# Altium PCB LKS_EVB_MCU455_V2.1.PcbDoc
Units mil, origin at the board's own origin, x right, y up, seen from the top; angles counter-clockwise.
Board outline 8180 x 3528.01 mil, 2 copper layers (Top Layer, Bottom Layer); 55 components, 86 nets, 295 pads, 79 vias.
Unrouted connection lines stored in the file: 39.
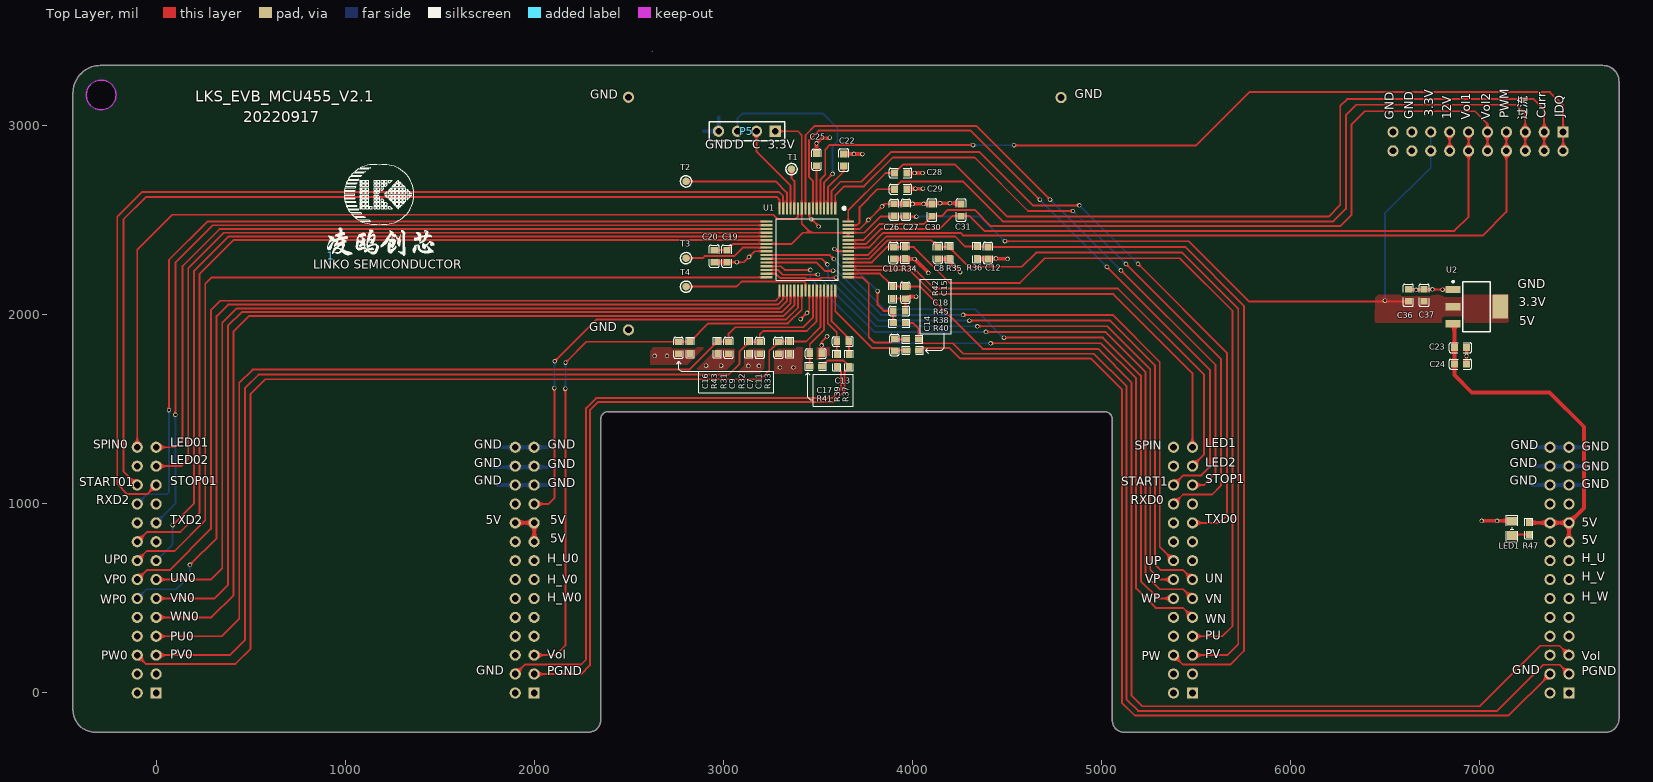
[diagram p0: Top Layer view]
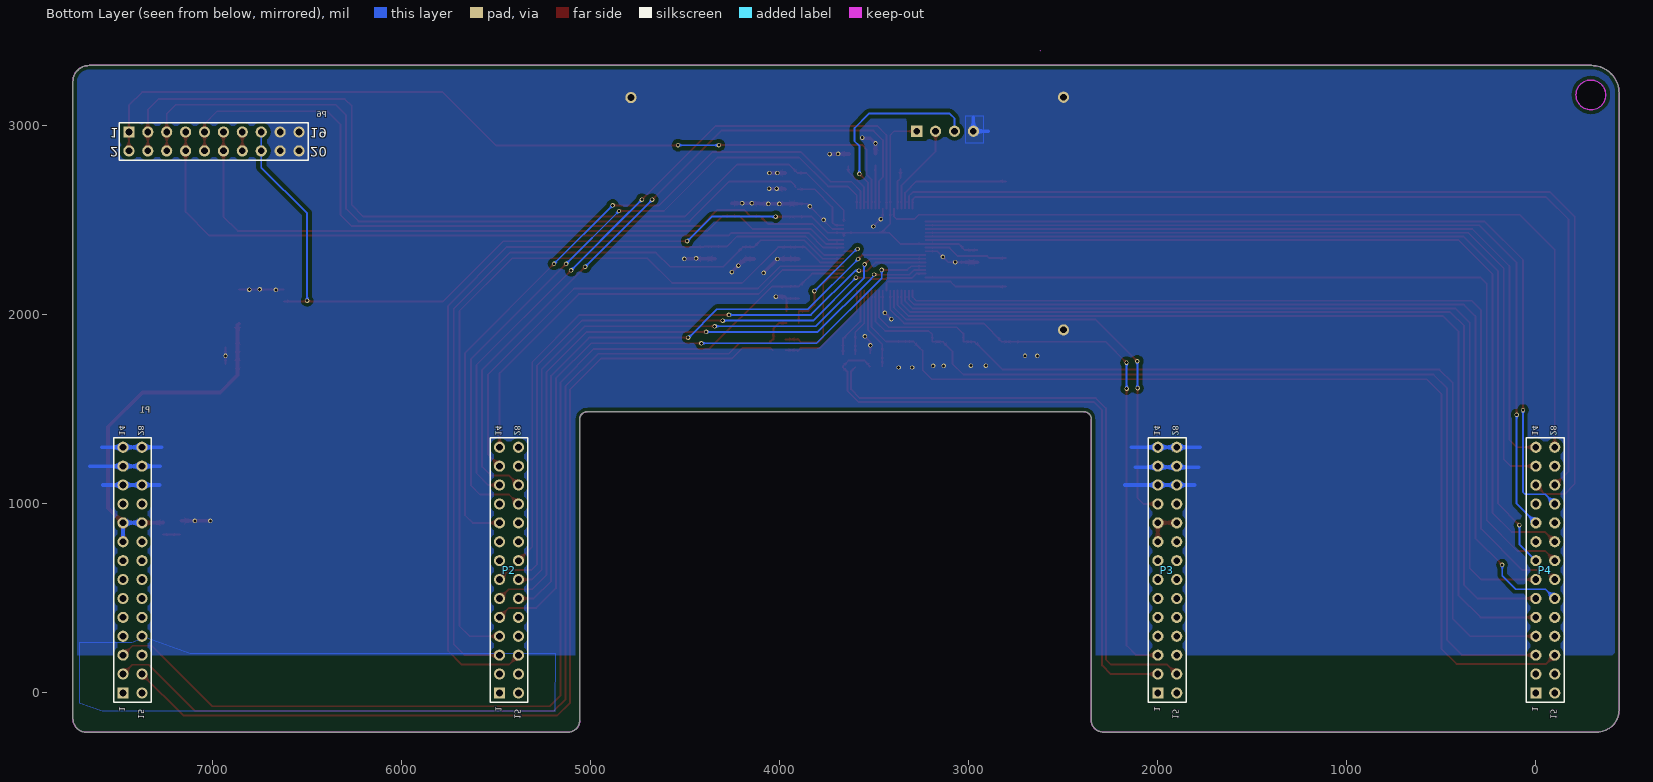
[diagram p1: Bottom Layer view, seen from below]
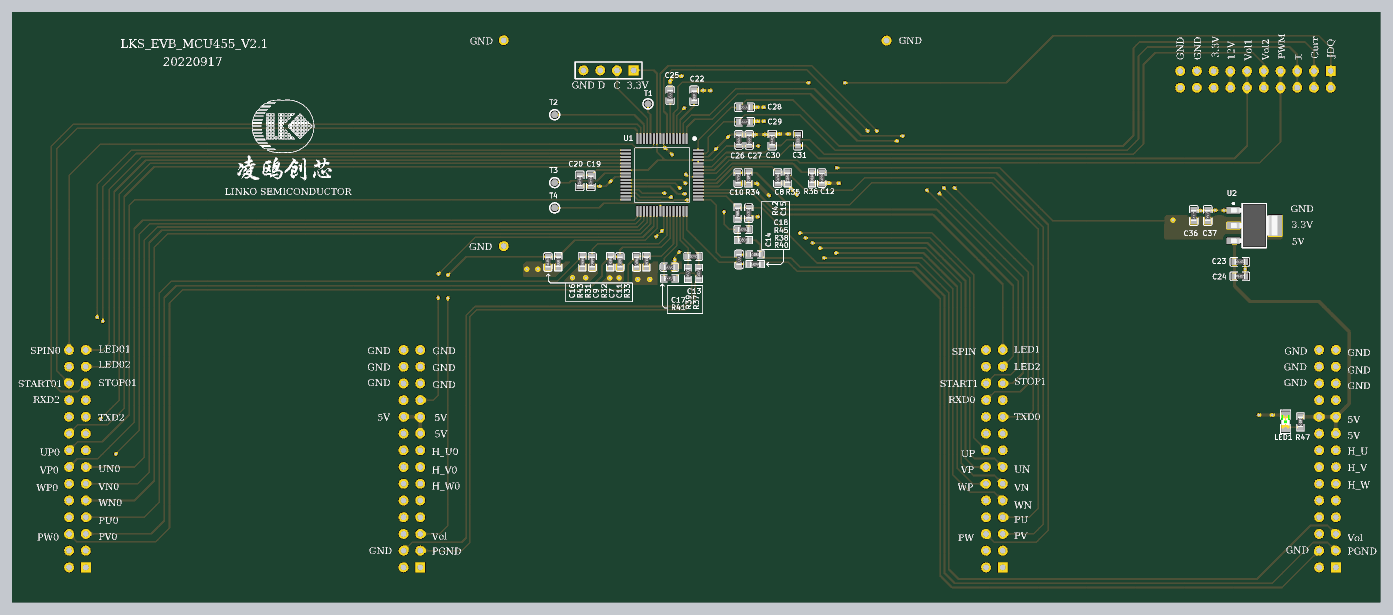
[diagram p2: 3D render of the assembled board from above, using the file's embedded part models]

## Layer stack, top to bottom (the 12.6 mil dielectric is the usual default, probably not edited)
Top Solder: solder mask 0.4, Solder Resist, Dk 3.5
Top Layer: signal copper 1.4
Dielectric1: dielectric 12.6, FR-4, Dk 4.8
Bottom Layer: signal copper 1.4
Bottom Solder: solder mask 0.4, Solder Resist, Dk 3.5

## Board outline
-440,-91 ccw(c-324,-91) -324,-207 2288.99,-207 ccw(c2288.99,-143.67) 2352.32,-143.67 2352.32,1448.33 cw(c2392,1448.33) 2392,1488.01 5018,1488.01 cw(c5018,1446.67) 5059.33,1446.67 5059.33,-146.33 ccw(c5121,-146.33) 5121,-208 7669,-208 ccw(c7669,-137) 7740,-137 7740,3235 ccw(c7654.99,3235) 7654.99,3320.01 -294.32,3320.01 ccw(c-294.32,3174.33) -440,3174.33
cut-out: -291,3085.26 cw(c-291,3164) -369.74,3164 cw(c-291,3164) -291,3242.74 cw(c-291,3164) -212.26,3164 cw(c-291,3164)

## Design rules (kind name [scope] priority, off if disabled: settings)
Clearance Clearance_1 [INPolygon] p1: gap=20 ignorepadtopadclearanceinfootprint=FALSE except(0: Arc-Hole Track-Hole SMDPad-Hole THPad-Hole Via-Hole Fill-Hole Poly-Hole Region-Hole Text-Hole)
Clearance [All] p2: gap=5 ignorepadtopadclearanceinfootprint=FALSE
ComponentClearance [All] p1: gap=0 collisioncheckmode=3 verticalgap=0 showdistances=FALSE
MinimumSolderMaskSliver [All] p1 off: minsoldermaskwidth=10
PolygonConnect [All] p1: connectstyle=Direct reliefconductorwidth=20 reliefentries=4 polygonreliefangle="90 Angle" airgapwidth=10
RoutingVias [All] p1: holewidth=12 width=20 viastyle="Through Hole" minholewidth=0 minwidth=10 maxholewidth=100 maxwidth=200
SilkToSilkClearance [All] p1 off: silktosilkclearance=10
SilkToSolderMaskClearance SilkscreenOverComponentPads [IsPad] p1 off: minsilkscreentomaskgap=10 clearancetoexposedcopper=TRUE
SolderMaskExpansion [All] p1: expansion=4 istentingtop=FALSE
Width [All] p1: maxlimit=100 minlimit=1 preferedwidth=10
26 further rules are at their usual default settings.

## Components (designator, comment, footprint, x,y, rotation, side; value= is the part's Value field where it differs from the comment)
1 "LKS_sign" LKS_LOGO2 924,2313 r0 top
C7 "1nF/16V" 0603C 3194,1826.01 r270 top
C8 "1nF/16V" 0603C 4137,2327.99 r270 top
C9 "1nF/16V" 0603C 3029,1826.01 r270 top
C10 "1nF/16V" 0603C 3900.5,2327.99 r270 top
C11 "1nF/16V" 0603C 3293,1826.01 r270 top
C12 "1nF/16V" 0603C 4400.67,2327.99 r270 top
C13 "1nF/10V" 0603C 3633,1859 r180 top
C14 "1nF/10V" 0603C 3906,1841 r270 top
C15 "100nF/50V" 0603C 3964,2118 r90 top
C16 "100nF/50V" 0603C 2763.33,1826.01 r90 top
C17 "1nF/50V" 0603C 3490,1795 r180 top
C18 "1nF/50V" 0603C 3932,2021 r180 top
C19 "10uF/10V" 0603C 3019.67,2310.99 r270 top
C20 "100nF/10V" 0603C 2953,2311 r270 top
C22 "100nF/10V" 0603C 3638,2820 r90 top
C23 "10uF/10V" 0603C 6901,1827 r0 top
C24 "100nF/10V" 0603C 6901,1740 r0 top
C25 "100nF/50V" 0603C 3494,2822 r90 top
C26 "10uF/10V" 0603C 3905,2556 r90 top
C27 "100nF/10V" 0603C 3967,2556 r90 top
C28 "100pF/10V" 0603C 3939,2751 r0 top
C29 "100pF/10V" 0603C 3939,2665 r0 top
C30 "100pF/10V" 0603C 4105,2555 r90 top
C31 "100pF/10V" 0603C 4259,2555 r90 top
C36 "10uF/10V" 0603C 6625,2104 r90 top
C37 "100nF/10V" 0603C 6709,2104 r90 top
LED1 "LED" LED_0805R 7174,871 r90 top
P1 "Header 14X2A" HDR2X14_CEN 7475,0 r90 bottom locked
P2 "Header 14X2A" HDR2X14_CEN 5483,0 r90 bottom locked
P3 "Header 14X2A" HDR2X14_CEN 2000,0 r90 bottom locked
P4 "Header 14X2A" HDR2X14_CEN 0,0 r90 bottom locked
P5 "Header 4" HDR1X4 3276,2972 r180 top
P6 "Header 10X2" HDR2X10 7444.02,2967.99 r180 bottom
R31 "1K" 0603R 2969,1827.51 r270 top value=K
R32 "1K" 0603R 3136,1827.51 r270 top value=K
R33 "1K" 0603R 3352,1827.51 r270 top value=K
R34 "1K" 0603R 3962,2329 r270 top value=K
R35 "1K" 0603R 4197,2329.49 r270 top value=K
R36 "1K" 0603R 4342,2329.49 r270 top value=K
R37 "1K1%" 0603R 3666,1758 r90 top value=K
R38 "1K1%" 0603R 4002,1871 r180 top value=K
R39 "1K1%" 0603R 3601.33,1758.01 r90 top value=K
R40 "1K1%" 0603R 4003,1813 r180 top value=K
R41 "1K1%" 0603R 3490,1728 r0 top value=K
R42 "1K1%" 0603R 3897,2119 r90 top value=K
R43 "1K1%" 0603R 2825,1827.51 r90 top value=K
R45 "1K1%" 0603R 3932,1957 r0 top value=K
R47 "330R" 0603R 7263,870 r270 top value=330
T1 "TestP" TP-40 3362,2772 r0 top
T2 "TestP" TP-40 2804,2707 r0 top
T3 "TestP" TP-40 2804,2301 r0 top
T4 "TestP" TP-40 2804,2150 r0 top
U1 "LKS32MC455RCT8" LQFP64 3593.17,2557.17 r180 top
U2 "AMS1117-3.3V" DCY0004A_M 6987,2044 r0 top

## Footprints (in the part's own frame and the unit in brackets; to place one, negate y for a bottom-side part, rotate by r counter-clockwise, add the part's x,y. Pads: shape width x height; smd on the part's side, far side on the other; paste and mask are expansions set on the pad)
0603C [mm]
  rect 0.9x0.95 smd: 1(-0.813,0) 2(0.813,0)
  silkscreen extent -1.42,-0.64 1.42,0.64, body extent -0.8,-0.4 0.8,0.4, height 0.45
0603R [mil]
  rect 38x32 smd: 1(-32,0) 2(32,0)
  silkscreen extent -55,-22 55,22, body extent -31,-16 32,16, height 18
DCY0004A_M [mm] "SOT223, 4-Leads, Body 6.7x3.7mm, Pitch 2.3mm, IPC Low Density"
  rrect10% 2.05x1 smd: 1(-3.175,2.3) 2(-3.175,0) 3(-3.175,-2.3)
  rrect5% 2.05x3.25 smd: 4(3.175,0)
  silkscreen extent -3.3,-3.35 1.85,3.47, body extent -3.5,-3.25 3.5,3.25, height 1.62
HDR1X4 [mm] "Connector; Header; 4 Position"
  rect 1.5x1.5 hole 0.9: 1(0,0)
  round 1.5 hole 0.9: 2(2.54,0) 3(5.08,0) 4(7.62,0)
  silkscreen extent -1.27,-1.27 8.89,1.27
HDR2X10 [mm] "Connector; Header; 10x2 Position"
  rect 1.5x1.5 hole 0.9: 1(0,0)
  round 1.5 hole 0.9: 2(0,-2.54) 3(2.54,0) 4(2.54,-2.54) 5(5.08,0) 6(5.08,-2.54) 7(7.62,0) 8(7.62,-2.54) 9(10.16,0) 10(10.16,-2.54) 11(12.7,0) 12(12.7,-2.54) 13(15.24,0) 14(15.24,-2.54) 15(17.78,0) 16(17.78,-2.54) 17(20.32,0) 18(20.32,-2.54) 19(22.86,0) 20(22.86,-2.54)
  silkscreen extent -1.27,-3.81 24.13,1.27
HDR2X14_CEN [mm] "Connector; Header; 14x2 Position"
  rect 1.5x1.5 hole 0.9: 1(0,0)
  round 1.5 hole 0.9: 2(2.54,0) 3(5.08,0) 4(7.62,0) 5(10.16,0) 6(12.7,0) 7(15.24,0) 8(17.78,0) 9(20.32,0) 10(22.86,0) 11(25.4,0) 12(27.94,0) 13(30.48,0) 14(33.02,0) 15(0,-2.54) 16(2.54,-2.54) 17(5.08,-2.54) 18(7.62,-2.54) 19(10.16,-2.54) 20(12.7,-2.54) 21(15.24,-2.54) 22(17.78,-2.54) 23(20.32,-2.54) 24(22.86,-2.54) 25(25.4,-2.54) 26(27.94,-2.54) 27(30.48,-2.54) 28(33.02,-2.54)
  silkscreen extent -1.27,-3.81 34.29,1.27
LED_0805R [mil] "LED"
  rect 46x51.18 smd: 1(-38,0) 2(38,0)
  silkscreen extent -70,-31 70,31, body extent -39,-25 39,25, height 32
LKS_LOGO2 [mil] "标?"
  silkscreen extent 70,167 440,482
LQFP64 [mm]
  rect 0.3x1.6 smd: 1(0,-0.15) 2(0.5,-0.15) 3(1,-0.15) 4(1.5,-0.15) 5(2,-0.15) 6(2.5,-0.15) 7(3,-0.15) 8(3.5,-0.15) 9(4,-0.15) 10(4.5,-0.15) 11(5,-0.15) 12(5.5,-0.15) 13(6,-0.15) 14(6.5,-0.15) 15(7,-0.15) 16(7.5,-0.15) 33(7.5,10.85) 34(7,10.85) 35(6.5,10.85) 36(6,10.85) 37(5.5,10.85) 38(5,10.85) 39(4.5,10.85) 40(4,10.85) 41(3.5,10.85) 42(3,10.85) 43(2.5,10.85) 44(2,10.85) 45(1.5,10.85) 46(1,10.85) 47(0.5,10.85) 48(0,10.85)
  rect 1.6x0.3 smd: 17(9.25,1.6) 18(9.25,2.1) 19(9.25,2.6) 20(9.25,3.1) 21(9.25,3.6) 22(9.25,4.1) 23(9.25,4.6) 24(9.25,5.1) 25(9.25,5.6) 26(9.25,6.1) 27(9.25,6.6) 28(9.25,7.1) 29(9.25,7.6) 30(9.25,8.1) 31(9.25,8.6) 32(9.25,9.1) 49(-1.75,9.1) 50(-1.75,8.6) 51(-1.75,8.1) 52(-1.75,7.6) 53(-1.75,7.1) 54(-1.75,6.6) 55(-1.75,6.1) 56(-1.75,5.6) 57(-1.75,5.1) 58(-1.75,4.6) 59(-1.75,4.1) 60(-1.75,3.6) 61(-1.75,3.1) 62(-1.75,2.6) 63(-1.75,2.1) 64(-1.75,1.6)
  silkscreen extent -1.37,-0.36 7.9,9.5
TP-40 [mil] "测试点"
  round 40 smd: 1(-0.39,-0.39)
  silkscreen extent -30,-30 30,30

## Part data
C7 C8 C9 C10 C11 C12: library part CAP, "Capacitor"
C13 C14 C15 C16 C17 C18 C19 C20 C22 C23 C24 C25 C26 C27 C28 C29 C30 C31 C36 C37: library part C, "Capacitor"
LED1: "LED_Light"
P1 P2 P3 P4: "Header, 14-Pin, Dual row"
P5: "Header, 4-Pin"
P6: "Header, 10-Pin, Dual row"
R31 R32 R33 R34 R35 R36 R37 R38 R39 R40 R41 R42 R43 R45 R47: library part Res, "Resistor"
T1 T2 T3 T4: "测试点"
U1: "芯片"
U2: library part CMP-019-00008-2, "Low-Dropout Linear Regulator, 1 A, 3.3 V, 0 to 125 degC, 4-Pin SOT223 (DCY), RoHS, Tape and Reel", Case/Package=SOT-223, Dropout Voltage=1.2V, Manufacturer="Texas Instruments", Max Input Voltage=15V, Max Operating Temperature=125°C, Max Ouput Current=1A, Min Input Voltage=2.5V, Min Operating Temperature=0°C, Min Supply Voltage=3.2V, Nominal Supply Current=5mA, Output Voltage=3.3V, Package Description="4-Pin Small Outline Transistor, Body 6.5 x 3.5 mm, Pitch 2.3 mm", Package Quantity=1000, Package Reference=DCY0004A

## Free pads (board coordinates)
  round 59.06 hole 35.43: 143(4788,3150) 144(2499,3152) 145(2499,1921)

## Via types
v1: diameter 23.62, hole 15.75, Top Layer to Bottom Layer, 79 vias

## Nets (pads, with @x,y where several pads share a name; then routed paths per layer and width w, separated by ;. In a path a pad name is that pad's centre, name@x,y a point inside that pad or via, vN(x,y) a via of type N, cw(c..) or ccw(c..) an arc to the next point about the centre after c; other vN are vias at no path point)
5V: P3.9 P3.10 P3.24 | length 200
  Top Layer w20: P3.24 P3.10 P3.9
12V: P6.13 P6.14 | length 100
  Top Layer w10: P6.14 P6.13
+3.3V: C19.1 C20.1 C26.1 C27.1 C36.1 C37.1 P5.1 P6.15 P6.16 U1.10 U1.23 U1.60 U1.61 U2.2 U2.4 | length 5628.8
  Top Layer w10: C20.1 C19.1 3020.66,2342.99 3053.73,2376.06 U1.23 3362.06,2376.06 3421.12,2435.12 3463,2435.12 ; P5.1 3396,2972 3416,2952 U1.10 3416,2482.12 3463,2435.12 ; U1.60 U1.61 ; C27.1 C27.1@3967.98,2524 ; v1(4022,2520) 3831,2520 3746.12,2435.12 U1.61 ; v1(4490,2390) 5464,2390 5782,2072 C36.1 ; 3463,2435.12 U1.61
  Bottom Layer w10: v1(4022,2520) 4360,2520 v1(4490,2390) ; v1(6501,2076) 6501,2537 6744.02,2780.02 P6.16 P6.15
+5V: C23.1 C24.1 P1.9 P1.10 P1.24 R47.1 U2.3 | length 2126.4
  Top Layer w20: U2.3 6869,1946.45 C23.1 C24.1 6869,1682 6961,1590 7372,1590 7554,1408 7554,979 P1.10 ; R47.1 7264,901 7474,901 P1.10 ; P1.9 P1.10
  Bottom Layer w20: P1.24 P1.10 P1.9
GND: C7.2 C8.2 C9.2 C10.2 C11.2 C12.2 C15.1 C16.1 C17.1 C18.1 C19.2 C20.2 C22.2 C23.2 C24.2 C25.2 C26.2 C27.2 C28.2 C29.2 C30.2 C31.2 C36.2 C37.2 LED1.2 P1.12 P1.13 P1.14 P1.26 P1.27 P1.28 P3.12 P3.13 P3.14 P3.26 P3.27 P3.28 P5.4 P6.17 P6.18 P6.19 P6.20 pad.143 pad.144 pad.145 R31.2 R32.2 R33.2 R34.2 R35.2 R36.2 R42.1 R43.1 U1.8 U1.25 U1.41 U1.62 U2.1 | length 5305.7
  Top Layer w9.84: C19.2 v1(3072,2278.99) 3108.99,2278.99 v1(3137.84,2307.84) 3166.69,2336.69 U1.25 ; v1(3410,1978) v1@3443.5,2011.5 ; v1(3444,2011) 3455.37,2022.37 U1.41 ; U1.8 3455.37,2518.63 v1@3511,2463 ; C17.1 3522,1859 v1(3550,1887) ; U1.62 3721.8,2454.8 3769,2502 v1(3841,2574) 3855,2588 C26.2 ; R42.1 3963,2087 C15.1 ; C18.1 C15.1 ; C15.1@3975,2097 C15.1 ; v1(4056,2751) v1@4057,2750 ; C30.2@4105,2588 C30.2@4108,2591 ; v1@4148,2589 v1@4150,2591 ; v1@4198,2591 v1@4200,2589 ; C31.2@4255,2591 C31.2 ; v1@4504.51,2297.49 v1(4505,2297) ; C36.2 6626.45,2134.55 U2.1 ; C24.2 C23.2 ; v1@3511,2463 3466,2508 v1@3511,2463
  Top Layer w19.68: C20.2 C19.2 ; C25.2 v1(3494,2908) 3521.36,2935.36 3561.36,2935.36 v1(3564,2938) ; C22.2@3634.02,2852 C22.2 v1(3691.5,2852) 3736,2852 v1(3737,2851) ; C10.2 v1(4013.01,2295.99) v1(4086,2223) ; C26.2 C27.2 v1(4002,2588) v1(4061,2588) C30.2@4105,2588 ; C29.2 3974,2668 v1(4017,2668) v1(4057,2668) ; C28.2 v1(4056,2751) ; C15.1@3975,2097 v1(4021,2097) ; C30.2@4108,2591 v1(4148,2591) ; C8.2 4185.01,2295.99 v1(4254,2227) ; v1@4150,2591 v1@4198,2591 ; v1(4200,2591) C31.2@4255,2591 ; R36.2 v1@4504.51,2297.49
  Top Layer w20: v1(7013.5,911) LED1.2@7166,911
  Bottom Layer w19.68: 1775,1300 P3.28 P3.14 2140,1300 ; 1783,1194 2119,1194 ; 1805,1100 P3.26 P3.12 2175,1100 ; 2897,2972 P5.4 2976,3046 ; 7271,1300 P1.28 P1.14 7588,1300 ; 7278,1200 P1.27 P1.13 7651,1200 ; 7282,1100 P1.26 P1.12 7583,1100
  other v1: 7095,911 3300,1722 3372,1722 3133,1730 3189,1731 2910,1732 2989,1732 2637,1783 2703,1783 6933,1783.5 3521,1839 6666,2133 6807,2134 6753,2135 4219.5,2261.5 4443,2299 3505,2468 3768,2503 3465,2507 4013.5,2751
GND0: P3.16 R39.1 | length 3254.9
  Top Layer w9.84: P3.16 1950,150 2248,150 2275,177 2275,1507 2328,1560 3576.95,1560 3623,1606.05 3623,1701.33 3601.33,1723.01 R39.1
GND1: P1.16 R40.1 | length 5212.4
  Top Layer w9.84: R40.1 4038,1813 4050,1825 4198,1825 4253,1770 4946,1770 5110,1606 5110,-51 5179,-120 7155,-120 P1.16
HU: P1.21
HU0: P3.21
HV: P1.20
HV0: P3.20
HW: P1.19
HW0: P3.19
JDQ: P6.1 P6.2 U1.5 | length 4624.9
  Top Layer w10: U1.5 3514.43,2716.43 3540,2742 3540,2875 3565,2900 4321,2900 v1(4323,2898) ; v1(4538.78,2898) 4539.78,2897 5502,2897 5784,3179 7374,3179 7444.02,3108.98 P6.1 P6.2
  Bottom Layer w10: v1(4323,2898) v1(4538.78,2898)
LDO12: C22.1 U1.3 | length 259.8
  Top Layer w10: U1.3 3553.8,2674.8 3638,2759 C22.1
LED1: P2.14 U1.51 | length 2439.2
  Top Layer w9.84: U1.51 3984.73,2238.27 4113,2110 5065,2110 5483,1692 P2.14
LED01: P4.14 U1.19 | length 4246.3
  Top Layer w9.84: P4.14 101,1300 140,1339 140,2259 335.8,2454.8 U1.19
LED2: P2.13 U1.52 | length 2630.4
  Top Layer w9.84: U1.52 3998.05,2257.95 4116,2140 5089,2140 5545,1684 5545,1263 5483,1201 P2.13
LED02: P4.13 U1.20 | length 4332.8
  Top Layer w9.84: P4.13 134,1200 170,1236 170,2247 358.12,2435.12 U1.20
LED3: P1.11
LED03: P3.11 U1.38 | length 2341
  Top Layer w9.84: P3.11 2077,1000 2107,1030 v1(2107,1613) ; v1(2109,1755) 2329,1975 3332,1975 3396.32,2039.32 U1.38
  Bottom Layer w9.84: v1(2107,1613) 2108,1614 2108,1754 v1(2109,1755)
NetLED1_1: LED1.1 R47.2 | length 89.4
  Top Layer w10: LED1.1@7174,839 7175,838 R47.2
NetT1_1: T1.1 U1.12 | length 214.8
  Top Layer w10: T1.1 3361.61,2723.39 3376.63,2708.37 U1.12
NetT2_1: T2.1 U1.14 | length 642.7
  Top Layer w10: T2.1 3278.39,2706.61 3337.26,2647.74 U1.14
NetT3_1: T3.1 U1.24 | length 448.5
  Top Layer w10: T3.1 2891.67,2300.61 2902.06,2311 3058,2311 3103.38,2356.38 U1.24
NetT4_1: T4.1 U1.40 | length 687.2
  Top Layer w10: T4.1 3070.17,2149.61 3097.56,2177 3428,2177 3435.69,2169.31 U1.40 U1.40@3434.78,2130.91
OC: C18.2 R45.1 U1.56 | length 631.8
  Top Layer w9.84: v1(3589,2349) 3592.73,2349 3605.04,2336.69 U1.56 ; v1(3817,2126) 3817,2053 3849,2021 C18.2 R45.1
  Bottom Layer w9.84: v1(3589,2349) 3594,2349 v1(3817,2126)
OC0: C17.2 R41.1 U1.45 | length 421.5
  Top Layer w9.84: R41.1 C17.2 3458,1846 3534.11,1922.11 U1.45@3534.11,2118.02
OPA2_IN: C14.2 R40.2 U1.48 | length 575.3
  Top Layer w9.84: U1.48 3593.17,2019.83 3788,1825 3890,1825 C14.2 ; C14.2@3906,1813 R40.2
OPA2_IP: C14.1 R38.2 U1.49 | length 623
  Top Layer w9.84: U1.49 3736.1,2198.9 3770,2165 3770,1883 3798,1855 3888,1855 C14.1 ; C14.1@3906,1871 R38.2
OPA3_IN: C13.2 R39.2 U1.46 | length 359.7
  Top Layer w9.84: U1.46 3553.8,1956.2 3601.33,1908.67 3601.33,1859 R39.2
OPA3_IP: C13.1 R37.2 U1.47 | length 378.3
  Top Layer w9.84: U1.47 3573.48,1965.52 3666,1873 R37.2
P10: P6.7 P6.8 U1.57 | length 3994.6
  Top Layer w9.84: U1.57 3769.38,2356.38 3846.9,2433.9 4256.1,2433.9 4270,2420 7019,2420 7144.02,2545.02 P6.8 P6.7
PE3: C29.1 P6.5 P6.6 U1.63 | length 4567.3
  Top Layer w10: U1.63 3707.49,2474.49 3722,2489 3722,2571 3816,2665 C29.1 ; C29.1@3915.76,2674.74 3919.72,2678.7 3919.72,2684.42 3942.3,2707 4267,2707 4479,2495 6229,2495 6295,2561 6295,3057 6350,3112 7197,3112 7244.02,3064.98 P6.5 P6.6
PFC_CURRENT: C28.1 P6.3 P6.4 U1.64 | length 4761.3
  Top Layer w10: U1.64 3662.06,2553.06 3860,2751 C28.1 3907,2751.98 3950.02,2795 4228,2795 4503,2520 6203,2520 6265,2582 6265,3106 6301,3142 7288,3142 7344.02,3085.98 P6.3 P6.4
PGND: P1.2 R38.1 R45.2 | length 5486.3
  Top Layer w9.84: R45.2 4005,1957 4034,1928 R38.1 4037,1871 4058,1850 4216,1850 4271,1795 4962,1795 5135,1622 5135,-34.95 5195.05,-95 7095,-95 7339,149 7426,149 P1.2
PGND0: P3.2 R37.1 R41.2 | length 3365.2
  Top Layer w9.84: P3.2 2249,100 2295,146 2295,1496 2339.28,1540.28 3585.28,1540.28 3643,1598 3643,1700 3666,1723 R37.1 3666,1729 3636.82,1758.18 3552.18,1758.18 3536.08,1742.08 3536.08,1739.08 3525,1728 R41.2
PGND1: P3.1
PGND2: P4.2
PGND3: P4.1
PGND4: P1.1
PGND5: P2.2
PGND6: P2.1
PU: C10.1 P2.4 R34.1 U1.53 | length 4217.5
  Top Layer w9.84: U1.53 3786.64,2277.64 3868.99,2359.99 C10.1 ; C10.1@3900.5,2359 4009,2359 4199,2169 4570,2169 4701,2300 5417,2300 5695,2022 5695,354 5641,300 P2.4
PU0: C9.1 P4.4 R31.1 U1.42 | length 5077.8
  Top Layer w9.84: P4.4 348,300 440,392 440,1641 510,1711 2820.49,1711 2954.92,1845.43 2957.92,1845.43 2969,1856.51 R31.1 2970.5,1858.01 C9.1 3029,1901 3063,1935 3425,1935 3474.85,1984.85 3474.85,2129.8 U1.42
PV: C8.1 P2.3 R35.1 U1.54 | length 4358
  Top Layer w9.84: U1.54 3773.32,2297.32 3871,2395 4101.01,2395 4136.02,2359.99 C8.1 4197,2360 4197,2358.49 4300.49,2255 4581,2255 4656,2330 5429,2330 5725,2034 5725,258 5667,200 P2.3
PV0: C7.1 P4.3 R32.1 U1.43 | length 5234.2
  Top Layer w9.84: P4.3 390,200 470,280 470,1613 542,1685 3029,1685 3087,1743 3087,1807.51 3136,1856.51 R32.1 3137.5,1858.01 C7.1 3194,1897 3212,1915 3442.86,1915 3494.74,1966.88 U1.43
PW: C12.1 P2.17 R36.1 U1.55 | length 4533.8
  Top Layer w9.84: U1.55 3765.01,2317.01 3863,2415 4228,2415 4281,2362 C12.1@4400.67,2362 ; C12.1 5444.01,2359.99 5755,2049 5755,222 5683,150 5433,150 P2.17
PW0: C11.1 P4.17 R33.1 U1.44 | length 5415.9
  Top Layer w9.84: P4.17 -54,154 420,154 500,234 500,1582 578,1660 3197,1660 3244,1707 3244,1810 3261.61,1827.61 3293.52,1859.51 R33.1 3438.51,1859.51 3514.43,1935.43 U1.44
RSTN: C25.1 U1.6 | length 227.6
  Top Layer w9.84: C25.1@3493.02,2790 3494.74,2788.28 U1.6
RXD0: P2.25 U1.1 | length 3596.8
  Top Layer w9.84: U1.1 3593.17,2632.4 3640.77,2680 3745,2680 3898,2833 4330,2833 4613,2550 v1(4851,2550) ; v1(5131,2270) 5635,1766 5635,1098 5587,1050 5433,1050 P2.25
  Bottom Layer w9.84: v1(4851,2550) v1(5131,2270)
RXD1: P4.23 U1.22 | length 4730.4
  Top Layer w9.84: P4.23 -48,852 129,852 230,953 230,2217 408.75,2395.75 U1.22
RXD2: P4.25 U1.17 | length 4669.4
  Top Layer w9.84: v1(68,1496) 68,2292 270.17,2494.17 U1.17
  Bottom Layer w9.84: P4.25 -49,1051 57,1051 68,1062 v1(68,1496) v1@68,1497
SPIN: P2.28
SPIN0: P4.28 U1.11 | length 4674
  Top Layer w9.84: P4.28 -100,2344 86,2530 3266,2530 3289,2507 3381,2507 3396.32,2522.32 U1.11
START1: P2.26 U1.7 | length 3780.7
  Top Layer w9.84: U1.7 3475.06,2708.94 3455,2729 3455,2925 3505,2975 4310,2975 v1(4675.38,2609.62) ; v1(5030,2255) 5575,1710 5575,1196 5530,1151 5434,1151 P2.26
  Bottom Layer w9.84: v1(4675.38,2609.62) v1(5030,2255)
START01: P4.26 U1.16 | length 5009.3
  Top Layer w9.84: P4.26 -173,1173 -173,2505 -53,2625 3283.48,2625 3297.89,2610.59 U1.16
STOP1: P2.12 U1.9 | length 4258.9
  Top Layer w9.84: U1.9 3435.69,2951.69 3484,3000 4340,3000 v1(4730,2610) ; v1(5104,2236.25) 5104.75,2236.25 5605,1736 5605,1163 5542,1100 P2.12
  Bottom Layer w9.84: v1(4730,2610) 5103.75,2236.25 v1(5104,2236.25) 5104,2237 4796,2545
STOP01: P4.12 U1.15 | length 5314
  Top Layer w9.84: P4.12 -48,1052 -152,1052 -206,1106 -206,2519 -75,2650 3297,2650 3317.57,2629.43 U1.15
SWCLK: P5.2 U1.13 | length 483.9
  Top Layer w9.84: P5.2 3176,2865 3356.95,2684.05 U1.13
SWDIO: P5.3 U1.4 | length 1094.1
  Top Layer w9.84: U1.4 3534.11,2702.11 v1(3579,2747)
  Bottom Layer w9.84: P5.3 3076,3040 3101,3065 3529,3065 3605,2989 3605,2920 3579,2894 v1(3579,2747)
TXD0: P2.10 U1.2 | length 3770.5
  Top Layer w9.84: U1.2 3573.48,2657.48 3621,2705 3731,2705 3889,2863 4355,2863 4638,2580 v1(4885,2580) ; v1(5195,2270) 5665,1800 5665,939 5626,900 P2.10
  Bottom Layer w9.84: v1(4885,2580) v1(5195,2270)
TXD1: P4.8 U1.21 | length 4719.8
  Top Layer w9.84: v1(87,888) 200,1001 200,2232 383.43,2415.43 U1.21
  Bottom Layer w9.84: P4.8 87,787 v1(87,888)
TXD2: P4.10 U1.18 | length 4628.3
  Top Layer w9.84: v1(102,1472) 102,2277 299.49,2474.49 U1.18
  Bottom Layer w9.84: P4.10 102,1002 v1(102,1472) v1@102,1472.27
UN: P2.7 U1.31 | length 3547.6
  Top Layer w9.84: U1.31 3278.42,2218.58 3302.21,2194.79 3435.37,2194.79 3440.77,2189.39 3511.19,2189.39 3518.8,2197 v1(3597,2197) ; v1(4303,1970) 5047,1970 5285,1732 5285,679 5313,651 5432,651 P2.7
  Bottom Layer w9.84: v1(3597,2197) 3824,1970 v1(4303,1970)
UN0: P4.7 U1.35 | length 4764
  Top Layer w9.84: P4.7 289,600 350,661 350,1958 427,2035 3299,2035 3337.26,2073.26 U1.35
UP: P2.22 U1.28 | length 3381.2
  Top Layer w9.84: U1.28 3493.36,2277.64 3538,2233 3581,2233 v1(3582,2234) ; v1(4270,2000) 5061,2000 5310,1751 5310,773 P2.22
  Bottom Layer w9.84: v1(3582,2234) 3602,2234 3836,2000 v1(4270,2000)
UP0: P4.22 U1.32 | length 4683.3
  Top Layer w9.84: P4.22 -49,751 98,751 260,913 260,2165 293.9,2198.9 U1.32
UP0-: P3.15
UP-: P1.15
VN: P2.6 U1.30 | length 3607.2
  Top Layer w9.84: U1.30 3289.73,2238.27 3315.49,2212.51 3499.51,2212.51 v1(3501,2214) ; v1(4390,1910) 5022,1910 5235,1697 5235,624 5310,549 5434,549 P2.6
  Bottom Layer w9.84: v1(3501,2214) 3501,2210.27 3507.05,2204.22 3507.05,2202.15 3525.39,2183.81 3799.2,1910 v1(4390,1910)
VN0: P4.6 U1.36 | length 4875.1
  Top Layer w9.84: P4.6 310,500 380,570 380,1942 453,2015 3309,2015 3356.95,2062.95 U1.36
Vol_1: C31.1 P6.11 P6.12 U1.58 | length 3854.2
  Top Layer w9.84: U1.58 3757.06,2376.06 3836,2455 4145,2455 4213,2523 C31.1 4304,2523 4382,2445 6869,2445 6944.02,2520.02 P6.12 P6.11
Vol_2: C30.1 P6.9 P6.10 U1.59 | length 4187.1
  Top Layer w9.84: U1.59 3741.75,2395.75 3827,2481 4062.02,2481 4104.02,2523 C30.1 4156,2523 4189,2556 4331,2556 4417,2470 6265,2470 6325,2530 6325,3008 6395,3078 6978,3078 7043.72,3012.28 7043.72,2968.29 P6.9 P6.10
VOL_ADC: C15.2 P1.3 R42.2 U1.50 | length 5886
  Top Layer w9.84: U1.50 3829.42,2218.58 3882.92,2165.08 3885.92,2165.08 3897,2154 R42.2 3963,2151 C15.2 4043,2150 4373,1820 4984,1820 5160,1644 5160,-12 5218,-70 7002,-70 7322,250 7425,250 P1.3
VOL_ADC0: C16.2 P3.3 R43.2 U1.39 | length 3151.5
  Top Layer w9.84: P3.3 2114,200 2165,251 v1(2165,1610) ; v1(2166,1748) 2276.01,1858.01 C16.2 2825,1858.01 2922,1955 3343,1955 3416,2028 U1.39
  Bottom Layer w9.84: v1(2165,1610) 2165.5,1610.5 2165.5,1747.5 v1(2166,1748)
VP: P2.21 U1.27 | length 3518.4
  Top Layer w9.84: U1.27 3522.68,2297.32 v1(3552,2268) ; v1(4345,1940) 5033,1940 5260,1713 5260,653 5313,600 P2.21
  Bottom Layer w9.84: v1(3552,2268) 3554.64,2265.36 3554.64,2196.36 3811,1940 v1(4345,1940)
VP0: P4.21 U1.33 | length 4730.5
  Top Layer w9.84: P4.21 -50,650 72,650 290,868 290,2026 339,2075 3278,2075 3297.89,2094.89 U1.33
VP0-: P4.15
VP-: P2.15
WN: P2.5 U1.29 | length 3699.6
  Top Layer w9.84: U1.29 3305.05,2257.95 3325,2238 v1(3461,2238) ; v1(4415,1850) 4999,1850 5185,1664 5185,553 5288,450 5433,450 P2.5
  Bottom Layer w9.84: v1(3461,2238) 3461,2195 3806,1850 v1(4415,1850)
WN0: P4.5 U1.37 | length 4956.3
  Top Layer w9.84: P4.5 292,400 410,518 410,1913 492,1995 3320,1995 3376.63,2051.63 U1.37
WP: P2.20 U1.26 | length 3543.4
  Top Layer w9.84: U1.26 3564.99,2317.01 v1(3586,2296) ; v1(4485,1880) 5009,1880 5210,1679 5210,592 5302,500 P2.20
  Bottom Layer w9.84: v1(3586,2296) 3852,2030 4333,2030 4483,1880 v1(4485,1880)
WP0: P4.20 U1.34 | length 4841.6
  Top Layer w9.84: v1(179,678) 320,819 320,1994 381,2055 3290,2055 3317.57,2082.57 U1.34
  Bottom Layer w9.84: P4.20 -51,549 106,549 178,621 178,677 v1(179,678)
WP0-: P4.16
WP-: P2.16
pads on no net: P1.4 P1.5 P1.6 P1.7 P1.8 P1.17 P1.18 P1.22 P1.23 P1.25 P2.8 P2.9 P2.11 P2.18 P2.19 P2.23 P2.24 P2.27 P3.4 P3.5 P3.6 P3.7 P3.8 P3.17 P3.18 P3.22 P3.23 P3.25 P4.9 P4.11 P4.18 P4.19 P4.24 P4.27

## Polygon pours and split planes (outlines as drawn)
GND on Top Layer "NONET_L-01_P-001" (solid, remove dead copper, pour order 13): 2614.66,1811.84 2630.66,1827.84 3573.84,1827.84 3573.84,1686.55 2613.73,1695.45
+3.3V on Top Layer "NONET_L-01_P-001" (solid, remove dead copper, pour order 12): 6449,2092 6465,2108 7156,2108 7156,1967 7149,1960 6454,1960 6448,1966
no net on Bottom Layer "NONET_L-01_P-001" (solid, remove dead copper, pour order 14): 2920,3051 2921,3052 3019,3052 3019,2910 2920,2910
GND on Bottom Layer "Bottom Layer-No Net" (solid, remove dead copper, pour order 8): 5185,207.74 6972.34,207.74 7118.64,207.74 7353.98,292 7430.31,264.67 7707,264.67 7707,-50.73 7586.15,-94 7582.97,-92.86 5188.18,-92.86
GND on Bottom Layer "Bottom Layer-No Net" (solid, remove dead copper, pour order 2): -465.05,3348 -465.05,261 -420.05,216 -404.05,200 297.95,200 7786.95,200 7832.95,246 7896.95,310 7896.95,3394

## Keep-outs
Keep-Out Layer:
  circle w3.94: c-291,3164 r78.74
  lines w3.94: 2623.01,3396.67 2624.01,3395.67 ; -440,-91 ccw(c-324,-91) -324,-207 2288.99,-207 ccw(c2288.99,-143.67) 2352.32,-143.67 2352.32,1448.33 cw(c2392,1448.33) 2392,1488.01 5018,1488.01 cw(c5018,1446.67) 5059.33,1446.67 5059.33,-146.33 ccw(c5121,-146.33) 5121,-208 7669,-208 ccw(c7669,-137) 7740,-137 7740,3235 ccw(c7654.99,3235) 7654.99,3320.01 -294.32,3320.01 ccw(c-294.32,3174.33) -440,3174.33 -440,-91

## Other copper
Bottom Layer:
  pour cut-out: 7325,1349 7525,1349 7526,1348 7526,1000 7325,1000
  pour cut-out: 1850,1350 2050,1350 2050,1000 1958,1000 1957,1001 1956,1000 1850,1000

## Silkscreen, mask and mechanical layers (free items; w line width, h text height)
Top Overlay:
  drawing of 38 lines, arcs and shapes, not listed
  text "GND" at 4861,3131 h80
  text "GND" at 2296,3128 h80
  text "LKS_EVB_MCU455_V2.1" at 207,3107 h100
  text "3.3V" at 6774,3048 h80 r90
  text "JDQ" at 7463,3047 h80 r90
  text "Curr" at 7369,3042 h80 r90
  text "PWM" at 7172,3040 h80 r90
  text "GND" at 6667,3035 h80 r90
  text "12V" at 6868,3035 h80 r90
  text "GND" at 6564,3034 h80 r90
  text "过流" at 7268,3034 h80 r90
  text "Vol2" at 7075,3033 h80 r90
  text "Vol1" at 6970,3032 h80 r90
  text "20220917" at 461,2999 h100
  text "GND" at 2905,2864 h80
  text "D" at 3061,2864 h80
  text "C" at 3155,2863 h80
  text "3.3V" at 3235,2863 h80
  text "GND" at 7204.07,2124.74 h80
  text "3.3V" at 7209,2030.74 h80
  text "5V" at 7211,1929.74 h80
  text "GND" at 2292,1898 h80
  text "LED01" at 75.07,1285.74 h80
  text "LED1" at 5551.07,1284 h80
  text "SPIN0" at -333.18,1277 h80
  text "GND" at 1684.25,1275.99 h80
  text "GND" at 2073,1275 h80
  text "GND" at 7166.07,1273.74 h80
  text "SPIN" at 5178.03,1271 h80
  text "GND" at 7544,1265 h80
  text "LED02" at 75.07,1193.74 h80
  text "LED2" at 5551.07,1180 h80
  text "GND" at 7163.07,1178.74 h80
  text "GND" at 1683.25,1177.99 h80
  text "GND" at 2072,1174 h80
  text "GND" at 7544,1160 h80
  text "STOP1" at 5551,1092.74 h80
  text "GND" at 1684.25,1084.99 h80
  text "GND" at 7163.07,1084.74 h80
  text "STOP01" at 75,1083.74 h80
  text "START1" at 5107,1079.74 h80
  text "START01" at -406,1077.74 h80
  text "GND" at 2073,1073 h80
  text "GND" at 7544,1066 h80
  text "RXD0" at 5157.07,983.74 h80
  text "RXD2" at -316.24,983 h80
  text "TXD0" at 5551,880.74 h80
  text "5V" at 1743,877.74 h80
  text "TXD2" at 75,877 h80
  text "5V" at 2084,875.74 h80
  text "5V" at 7543.93,864.74 h80
  text "5V" at 2085,777.74 h80
  text "5V" at 7543.93,769.74 h80
  text "H_U" at 7544,675 h80
  text "H_U0" at 2069,673 h80
  text "UP0" at -274.95,669 h80
  text "UP" at 5232.87,661 h80
  text "H_V" at 7544,577 h80
  text "UN0" at 75,570 h80
  text "UN" at 5551,567 h80
  text "VP" at 5232.35,565 h80
  text "VP0" at -275.46,562 h80
  text "H_V0" at 2069,562 h80
  text "H_W" at 7544,473 h80
  text "H_W0" at 2069,466 h80
  text "VN0" at 75,464 h80
  text "WP" at 5212,461 h80
  text "VN" at 5551,459 h80
  text "WP0" at -295.81,457 h80
  text "WN0" at 75.07,367 h80
  text "WN" at 5551.07,352 h80
  text "PU" at 5551.07,265 h80
  text "PU0" at 75.07,261 h80
  text "PV" at 5551.07,169 h80
  text "Vol" at 2068.93,166 h80
  text "PV0" at 75.07,165 h80
  text "PW0" at -290.71,161 h80
  text "PW" at 5215.33,157 h80
  text "Vol" at 7543.93,157 h80
  text "GND" at 7175.07,83.74 h80
  text "GND" at 1693.07,79.74 h80
  text "PGND" at 2070.07,76.74 h80
  text "PGND" at 7544,76.74 h80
